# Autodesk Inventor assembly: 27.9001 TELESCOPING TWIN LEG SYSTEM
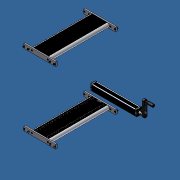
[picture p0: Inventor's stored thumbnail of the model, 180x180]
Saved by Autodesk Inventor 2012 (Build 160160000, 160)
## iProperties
Created: 2013-12
Part Number: 27.9001 TELESCOPING TWIN LEG SYSTEM
Document SubType Name: Assembly
Designer: Admin
Author: Admin
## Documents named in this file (4)
- C:\Andys Backup Data\ANDY'S INVENTOR\INVENTOR LIBRARIES\PARTS LIBRARY\HYDRAULIC VERTICAL ADJUSTMENT\27.9001Telescoping Twin Leg System\27.9001 TELESCOPING TWIN LEG SYSTEM.iam
- C:\Andys Backup Data\ANDY'S INVENTOR\INVENTOR LIBRARIES\PARTS LIBRARY\HYDRAULIC VERTICAL ADJUSTMENT\27.9001Telescoping Twin Leg System\27.9001 LEG ASSY COMPLETE.iam
- C:\Andys Backup Data\ANDY'S INVENTOR\INVENTOR LIBRARIES\PARTS LIBRARY\HYDRAULIC VERTICAL ADJUSTMENT\27.9001Telescoping Twin Leg System\PUMP ASSY COMPLETE.iam
- C:\Andys Backup Data\ANDY'S INVENTOR\INVENTOR LIBRARIES\PARTS LIBRARY\30 SERIES\21.9160_1 M6 ECONO-NUT 30 SS.ipt
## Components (7 placed, 3 different names)
1. 27.9001 LEG ASSY COMPLETE:1 [sub-assembly] — Flush:1, Flush:2, Angle:1, Flush:3, Mate:1, Mate:2, Mate:3, Mate:4
2. 27.9001 LEG ASSY COMPLETE:2 [sub-assembly] — Flush:1, Flush:2, Mate:5, Mate:6, Mate:7, Mate:8
3. PUMP ASSY COMPLETE:1 [sub-assembly] — Angle:1, Flush:3
4. 21.9160_1 M6 ECONO-NUT 30 SS:1 — Mate:1, Mate:2
5. 21.9160_1 M6 ECONO-NUT 30 SS:2 — Mate:3, Mate:4
6. 21.9160_1 M6 ECONO-NUT 30 SS:3 — Mate:7, Mate:8
7. 21.9160_1 M6 ECONO-NUT 30 SS:4 — Mate:5, Mate:6
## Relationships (12: Mate 8, Flush 3, Angle 1)
- Flush:1: 27.9001 LEG ASSY COMPLETE:1 ↔ 27.9001 LEG ASSY COMPLETE:2
- Flush:2: 27.9001 LEG ASSY COMPLETE:1 ↔ 27.9001 LEG ASSY COMPLETE:2
- Angle:1: 27.9001 LEG ASSY COMPLETE:1 ↔ PUMP ASSY COMPLETE:1
- Flush:3: 27.9001 LEG ASSY COMPLETE:1 ↔ PUMP ASSY COMPLETE:1
- Mate:1: 27.9001 LEG ASSY COMPLETE:1 ↔ 21.9160_1 M6 ECONO-NUT 30 SS:1
- Mate:2: 27.9001 LEG ASSY COMPLETE:1 ↔ 21.9160_1 M6 ECONO-NUT 30 SS:1
- Mate:3: 27.9001 LEG ASSY COMPLETE:1 ↔ 21.9160_1 M6 ECONO-NUT 30 SS:2
- Mate:4: 27.9001 LEG ASSY COMPLETE:1 ↔ 21.9160_1 M6 ECONO-NUT 30 SS:2
- Mate:5: 27.9001 LEG ASSY COMPLETE:2 ↔ 21.9160_1 M6 ECONO-NUT 30 SS:4
- Mate:6: 27.9001 LEG ASSY COMPLETE:2 ↔ 21.9160_1 M6 ECONO-NUT 30 SS:4
- Mate:7: 27.9001 LEG ASSY COMPLETE:2 ↔ 21.9160_1 M6 ECONO-NUT 30 SS:3
- Mate:8: 27.9001 LEG ASSY COMPLETE:2 ↔ 21.9160_1 M6 ECONO-NUT 30 SS:3
